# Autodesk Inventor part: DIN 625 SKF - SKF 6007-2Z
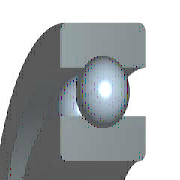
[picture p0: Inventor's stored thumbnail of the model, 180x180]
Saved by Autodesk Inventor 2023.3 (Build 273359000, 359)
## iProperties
IsCustomPart: 0
Created: 2022-02
Part Number: DIN 625 SKF - SKF 6007-2Z
Material: Acier, doux
Description: Roulements à une rangée de billes à gorge profonde avec deux flasques Z SKF
Document SubType Name: Modeling
Standard: DIN 625 SKF
Designer: Thier
Standard Revision: SKF 2013
Standards Organization: DIN
Language: fr-FR
Size Designation: SKF 6007-2Z
Categories: <MemberInstance><Categories><Category DisplayName="Pièces d'arbre" InternalName="7f7aeb1f-a693-4053-b835-cee3144e0d98" Mnemonic="SHFT"><Category DisplayName="Ro
Density: 7.85 g/cm^3
Appearance: Semi-poli
Author: Thier
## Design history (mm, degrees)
node "WorkPoint1"
node "WorkAxis1"
node "WorkPlane3"
node "WorkPlane4"
node "WorkPoint2"
pattern_circular "RéseauPolaire1" dims "d17" = 93.81481 (= msp_pocet), angle "d19" = 360 deg
body "Solid1"
node "Esquisse1"
revolve "Révolution1" stored, may be unused: angle "d6" = 360 deg
revolve "Révolution2" stored, may be unused: angle "d10" = 360 deg
node "Esquisse4"
revolve "Révolution3" stored, may be unused: angle "d16" = 360 deg
fillet "Congé1" dims "d20" = 1 (= r)
sketch "Esquisse2"
  geometry: L1 (17.5, 14)-(31, 14); L2 (17.5, 0)-(17.5, 14); L3 (31, 0)-(17.5, 0); L4 (31, 14)-(31, 0); L5 (0, 0)-(0, 20); L6 (0, 0)-(0, 20); L7 (-7.2, 0)-(43.2, 0) reference
  constraints: 12 end point, 3 vertical, 2 horizontal, 1 collinear, 1 other
  dimensions: "d1" = 35 diameter of L1.start L5 (= Diam); "d3" = 62 diameter of L1.end L5 (= DD); "d5" = 14 distance of L2.start L1.start (= msp_mdtd2)
sketch "Esquisse3"
  geometry: L1 (26.68, 14)-(26.68, 10.24); L2 (21.82, 14)-(26.68, 14); L3 (21.82, 10.24)-(21.82, 14); L4 (21.82, 0)-(21.82, 3.76); L5 (26.68, 0)-(21.82, 0); L6 (26.68, 3.76)-(26.68, 0); L7 (31, 0)-(-31, 0) reference; L8 (31, 14)-(-31, 14) reference; L9 (0, -42.29)-(0, 61.29); L10 (0, 82.007)-(0, -63.007) reference; A1 r 4.05 centre (24.25, 7) between (26.68, 3.76) and (26.68, 10.24); A2 r 4.05 centre (24.25, 7) between (21.82, 10.24) and (21.82, 3.76)
  constraints: 14 end point, 4 collinear, 4 point on circle, 4 vertical, 2 centre point, 2 concentric, 2 horizontal, 2 point on line
  dimensions: "d9" = 8.1 diameter of A1 (= msp_mdtd6); "d21" = 21.82 distance between parallel lines of L9 L4 (= 0.5 x msp_d1); "d22" = 24.25 distance from line of L9 A1.centre (= 0.5 x msp_ds); "d23" = 26.68 distance between parallel lines of L9 L6 (= 0.5 x msp_dd1)
sketch "Esquisse5"
  geometry: L1 (24.25, 2.95)-(24.25, 11.05); L2 (26.68, 0)-(-26.68, 0) reference; L3 (24.25, 2.95)-(24.25, 11.05); A1 r 4.05 centre (24.25, 7) between (24.25, 2.95) and (24.25, 11.05); A2 r 4.05 centre (24.25, 7) between (26.68, 3.76) and (26.68, 10.24) reference
  constraints: 4 end point, 2 point on circle, 1 centre point, 1 concentric, 1 vertical
  dimensions: "d13" = 0 horizontal distance of A1.centre L1.start; "d15" = 8.1001 diameter of A1 (computed from msp_mdtd6)
other parameters: "Diam" = 35 [user parameter; used in 3 equation terms], "DD" = 62 [user parameter; used in 3 equation terms], "B" = 14 [user parameter; used in 1 equation term], "r" = 1 [user parameter; used in 1 equation term], "msp_ds" = 48.5 (= 0.5 x Diam + 0.5 x DD) [user parameter; used in 5 equation terms], "msp_d0" = 8.1 (= -0.3 x Diam + 0.3 x DD) [user parameter; used in 4 equation terms], "msp_d1" = 43.64 (= msp_ds - 0.6 x msp_d0) [user parameter; used in 1 equation term], "msp_dd1" = 53.36 (= msp_ds + 0.6 x msp_d0) [user parameter; used in 1 equation term], "msp_pom" = 72.75 (= 1.5 x msp_ds) [user parameter; used in 1 equation term], "msp_mdtd2" = 14 (= B) [user parameter; used in 3 equation terms], "msp_mdtd4" = 48.5 (= msp_ds) [user parameter], "msp_mdtd6" = 8.1 (= msp_d0) [user parameter; used in 2 equation terms], "msp_mdtd7" = 7 (= 0.5 x msp_mdtd2) [user parameter], "msp_pocet" = 93.81481 (computed from msp_d0, msp_pom) [user parameter; used in 1 equation term], "d2" = 72 (derived), "d4" = 19 (derived), "d7" = 0, "d8" = 15.6 (derived), "d11" = -14 (computed from msp_mdtd2), "d12" = 0 (derived), "d14" = 15.6001 (derived), "d26" = 0, "d27" = 0, "d28" = 0, "d29" = 0, "d30" = 0
